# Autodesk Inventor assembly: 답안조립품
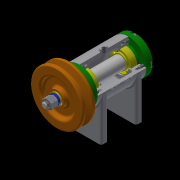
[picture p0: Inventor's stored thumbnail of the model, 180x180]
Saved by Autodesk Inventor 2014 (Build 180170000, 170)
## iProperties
Created: 2020-07
Part Number: 답안조립품
Document SubType Name: Assembly
Designer: kh
Author: kh
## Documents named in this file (15)
- C:\Users\kh\Desktop\700706V1020\답안조립품.iam
- C:\Users\kh\Desktop\700706V1020\본체.ipt
- C:\Users\kh\Desktop\700706V1020\베어링 6002.ipt
- C:\Users\kh\Desktop\700706V1020\뒤커버.ipt
- C:\Users\kh\Desktop\700706V1020\앞커버.ipt
- C:\Users\kh\Desktop\700706V1020\축.ipt
- C:\Users\kh\Desktop\700706V1020\오일 실 15 25 7.ipt
- C:\Users\kh\Desktop\700706V1020\키 3x3x12.ipt
- C:\Users\kh\Desktop\700706V1020\V벨트풀리.ipt
- C:\Users\kh\Desktop\700706V1020\와셔 8x17.ipt
- C:\Users\kh\Desktop\700706V1020\스프링와셔 8.ipt
- C:\Users\kh\Desktop\700706V1020\너트 M8.ipt
- C:\Users\kh\Desktop\700706V1020\와셔 6x11.5.ipt
- C:\Users\kh\Desktop\700706V1020\볼트 M6x8.ipt
- C:\Users\kh\Desktop\700706V1020\볼트 M4x12.ipt
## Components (1 placed, 1 different names)
1. V벨트풀리:1 — Mate:17, Mate:18, Mate:20, Mate:25
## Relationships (4: Mate 4)
- Mate:17: V벨트풀리:1
- Mate:18: V벨트풀리:1
- Mate:20: V벨트풀리:1
- Mate:25: V벨트풀리:1
